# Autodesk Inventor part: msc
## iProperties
Shininess: 64.0
Length Units: 11269
Angle Units: 11279
Time Units: 11290
Mass Units: 11283
Length Display Precision: 3
Angle Display Precision: 2
Compacted: True
Part Number: msc
Document SubType Name: Modeling
Created: 2004-07
Designer: Peter
Manufacturer: Standard
Standards Organization: Custom
Density: 0.0
Volumn: 0.0
Area: 0.0
PropertySet Name: Model Information
Control State: 0
Master: False
Checked Out: False
Author: Peter
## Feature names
1. Extrusion1
